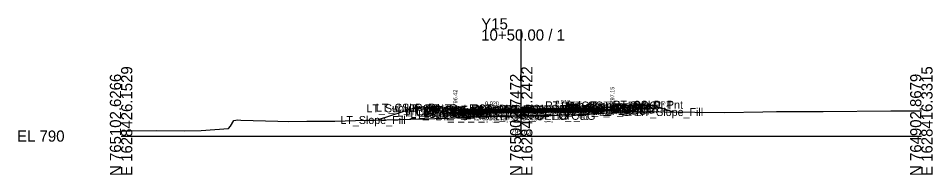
# Model space of a CAD drawing. Extents: x -26 to 203, y -10 to 2522.
# Drawn here: x -25.7 to 202.8, y 990.3 to 1029.5 of the extents above; entities that cross this region are included whole.
import ezdxf

# ---------------------------------------------------------------- set-up
doc = ezdxf.new("R2010")
doc.units = 0
for name, color, linetype in [('Default', 7, 'Continuous'), ('Exist CMT Pavement', 7, 'Continuous'), ('Exist Cross Section Cell', 7, 'Continuous'), ('Exist XS Center Line Elevation Label', 7, 'Continuous'), ('Exist XS Ground Line', 7, 'Continuous'), ('Prop CMT Conc Surface', 7, 'Continuous'), ('Prop CMT Concrete Structures', 7, 'Continuous'), ('Prop CMT Pvmt Course 1', 7, 'Continuous'), ('Prop CMT Pvmt Course 1 CG', 7, 'Continuous'), ('Prop CMT Pvmt Course 1 Wedge', 7, 'Continuous'), ('Prop CMT Pvmt Course 2', 7, 'Continuous'), ('Prop CMT Pvmt Course 2 Wedge', 7, 'Continuous'), ('Prop CMT Pvmt Course 3', 7, 'Continuous'), ('Prop CMT Pvmt Course 3 Wedge', 7, 'Continuous'), ('Prop CMT Pvmt Surface', 7, 'Continuous'), ('Prop CMT Pvmt Wedge Surface 1', 7, 'Continuous'), ('Prop CMT Pvmt Wedge Surface 2', 7, 'Continuous'), ('Prop CMT Pvmt Wedge Surface 3', 7, 'Continuous'), ('Prop CMT Slope Grass', 7, 'Continuous'), ('Prop CMT Subgrade Earthwork', 7, 'Continuous'), ('Prop XS Hydro Elevations', 7, 'Continuous'), ('Prop XS SE Text', 7, 'Continuous'), ('Prop XS Side Slope Text', 7, 'Continuous'), ('Scratch_Level_0', 7, 'Continuous')]:
    doc.layers.add(name, color=color, linetype=linetype)

msp = doc.modelspace()

# ---------------------------------------------------------------- linework, layer by layer
at = {"layer": 'Exist CMT Pavement'}
for points in [[(100, 1005.03), (97.47, 1005.02), (93.61, 1004.96)], [(100, 1005.03), (106.07, 1005.07)]]:
    msp.add_lwpolyline(points, dxfattribs=at)
at = {"layer": 'Exist Cross Section Cell'}
for p, q in [((100, 1000), (100, 1026.72)), ((0, 1000), (100, 1000)), ((100, 1000), (200, 1000))]:
    msp.add_line(p, q, dxfattribs=at)
at = {"layer": 'Exist XS Ground Line'}
msp.add_lwpolyline([(0, 1001.31), (2.3, 1001.35), (8.93, 1001.42), (15.94, 1001.31), (20.04, 1001.43), (26.82, 1001.87), (27.31, 1002.52), (28.21, 1003.89), (29.2, 1004.06), (29.91, 1003.96), (39.18, 1003.76), (41.81, 1003.68), (46.46, 1003.71), (53.42, 1003.77), (61.16, 1003.96), (63.29, 1004.01), (75.46, 1004.3), (78.43, 1004.39), (81.9, 1004.51), (89.39, 1004.87), (91.26, 1004.91), (93.18, 1005.01), (93.61, 1004.96), (97.47, 1005.02), (100, 1005.03), (106.07, 1005.07), (110.25, 1005.34), (111.48, 1005.34), (114.03, 1005.39), (115.06, 1005.39), (119.22, 1005.62), (125.22, 1006.04), (127.02, 1006.11), (128.5, 1006.12), (150.81, 1005.9), (160.35, 1006.1), (163.8, 1006.17), (175.48, 1006.17), (192.39, 1006.31), (199.37, 1006.34), (200, 1006.34)], dxfattribs=at)
at = {"layer": 'Prop CMT Conc Surface'}
for points in [[(83.51, 1006.42), (83.51, 1006.92), (83.01, 1006.92)], [(85.51, 1006.54), (83.51, 1006.42)], [(120.76, 1007.19), (122.76, 1007.15)], [(122.76, 1007.15), (122.76, 1007.65), (123.26, 1007.65)]]:
    msp.add_lwpolyline(points, dxfattribs=at)
at = {"layer": 'Prop CMT Concrete Structures'}
for points in [[(85.51, 1006.54), (83.51, 1006.42), (83.51, 1006.92), (83.01, 1006.92)], [(83.01, 1006.92), (83.01, 1005.91), (85.51, 1005.96)], [(85.51, 1005.96), (85.51, 1006.54)], [(120.76, 1007.19), (122.76, 1007.15), (122.76, 1007.65), (123.26, 1007.65)], [(123.26, 1007.65), (123.26, 1006.65), (120.76, 1006.61)], [(120.76, 1006.61), (120.76, 1007.19)]]:
    msp.add_lwpolyline(points, dxfattribs=at)
at = {"layer": 'Prop CMT Pvmt Course 1'}
for points in [[(100, 1006.83), (85.51, 1006.54)], [(85.51, 1006.29), (100, 1006.58)], [(85.51, 1006.54), (85.51, 1006.29)], [(100, 1006.83), (120.76, 1007.19)], [(120.76, 1006.94), (100, 1006.58)], [(100, 1006.58), (100, 1006.83)], [(100, 1006.58), (100, 1006.83)], [(100, 1006.7), (100, 1006.58), (100, 1006.58)], [(100, 1006.7), (100, 1006.58), (100, 1006.58)], [(120.76, 1007.19), (120.76, 1006.94)]]:
    msp.add_lwpolyline(points, dxfattribs=at)
at = {"layer": 'Prop CMT Pvmt Course 1 CG'}
for points in [[(85.51, 1005.96), (82.51, 1005.9), (82.17, 1005.56)], [(82.17, 1005.56), (85.51, 1005.62)], [(85.51, 1005.62), (85.51, 1005.96)], [(120.76, 1006.61), (123.76, 1006.66), (124.09, 1006.33)], [(120.76, 1006.28), (120.76, 1006.61)], [(124.09, 1006.33), (120.76, 1006.28)]]:
    msp.add_lwpolyline(points, dxfattribs=at)
at = {"layer": 'Prop CMT Pvmt Course 1 Wedge'}
for points in [[(100, 1006.7), (100, 1006.58)], [(100, 1006.58), (100, 1006.7)]]:
    msp.add_lwpolyline(points, dxfattribs=at)
at = {"layer": 'Prop CMT Pvmt Course 2'}
for points in [[(100, 1006.58), (85.51, 1006.29)], [(85.51, 1006.29), (85.51, 1005.96)], [(85.51, 1005.96), (100, 1006.25)], [(100, 1006.58), (120.76, 1006.94)], [(120.76, 1006.61), (100, 1006.25)], [(120.76, 1006.94), (120.76, 1006.61)]]:
    msp.add_lwpolyline(points, dxfattribs=at)
at = {"layer": 'Prop CMT Pvmt Course 2 Wedge'}
for points in [[(100, 1006.58), (100, 1006.25)], [(100, 1006.25), (100, 1006.58)]]:
    msp.add_lwpolyline(points, dxfattribs=at)
at = {"layer": 'Prop CMT Pvmt Course 3'}
for points in [[(100, 1006.25), (85.51, 1005.96)], [(85.51, 1005.96), (85.51, 1005.62)], [(85.51, 1005.62), (100, 1005.91)], [(100, 1006.25), (120.76, 1006.61)], [(120.76, 1006.28), (100, 1005.91)], [(120.76, 1006.61), (120.76, 1006.28)]]:
    msp.add_lwpolyline(points, dxfattribs=at)
at = {"layer": 'Prop CMT Pvmt Course 3 Wedge'}
for points in [[(100, 1006.25), (100, 1005.03)], [(100, 1005.03), (100, 1006.25)], [(100, 1005.03), (97.47, 1005.02), (93.61, 1004.96)], [(106.07, 1005.07), (100, 1005.03)]]:
    msp.add_lwpolyline(points, dxfattribs=at)
at = {"layer": 'Prop CMT Pvmt Surface'}
for points in [[(100, 1006.83), (85.51, 1006.54)], [(100, 1006.83), (120.76, 1007.19)]]:
    msp.add_lwpolyline(points, dxfattribs=at)
at = {"layer": 'Prop CMT Pvmt Wedge Surface 1'}
for points in [[(100, 1006.58), (85.51, 1006.29)], [(85.51, 1006.29), (85.51, 1006.54)], [(100, 1006.58), (120.76, 1006.94)], [(120.76, 1006.94), (120.76, 1007.19)]]:
    msp.add_lwpolyline(points, dxfattribs=at)
at = {"layer": 'Prop CMT Pvmt Wedge Surface 2'}
for points in [[(85.51, 1006.29), (85.51, 1006.54)], [(120.76, 1006.94), (120.76, 1007.19)]]:
    msp.add_lwpolyline(points, dxfattribs=at)
at = {"layer": 'Prop CMT Pvmt Wedge Surface 3'}
for points in [[(85.51, 1005.96), (85.51, 1006.54)], [(120.76, 1006.61), (120.76, 1007.19)]]:
    msp.add_lwpolyline(points, dxfattribs=at)
at = {"layer": 'Prop CMT Slope Grass'}
for points in [[(123.26, 1007.65), (132.76, 1007.84), (138.21, 1006.02)], [(83.01, 1006.92), (73.51, 1007.11), (64.28, 1004.03)]]:
    msp.add_lwpolyline(points, dxfattribs=at)
at = {"layer": 'Prop CMT Subgrade Earthwork'}
for points in [[(85.51, 1005.62), (82.17, 1005.56), (80.77, 1006.96)], [(100, 1005.91), (85.51, 1005.62)], [(100, 1005.91), (120.76, 1006.28)], [(120.76, 1006.28), (124.09, 1006.33), (125.44, 1007.69)]]:
    msp.add_lwpolyline(points, dxfattribs=at)

# ---------------------------------------------------------------- texts
at = {"layer": 'Default'}
msp.add_text('-', height=0.0001, dxfattribs=at).set_placement((0, 1000))
at = {"layer": 'Exist Cross Section Cell'}
for s, p in [('Y15', (90, 1026.72)), ('10+50.00 / 1', (90, 1023.92)), ('EL 790', (-26, 998.6))]:
    msp.add_text(s, height=2.8, dxfattribs=at).set_placement(p)
for s, p in [('E 1628426.1529', (2.8, 990)), ('E 1628421.2422', (102.8, 990)), ('E 1628416.3315', (202.8, 990)), ('N 765102.6266', (0, 990)), ('N 765002.7472', (100, 990)), ('N 764902.8679', (200, 990))]:
    msp.add_text(s, height=2.8, rotation=90, dxfattribs=at).set_placement(p)
at = {"layer": 'Exist XS Center Line Elevation Label'}
msp.add_text('795.03', height=1.2, dxfattribs=at).set_placement((97.42, 1000.43))
at = {"layer": 'Prop XS Hydro Elevations'}
for s, p in [('796.42', (84.01, 1007.42)), ('797.15', (123.26, 1008.15))]:
    msp.add_text(s, height=1, rotation=90, dxfattribs=at).set_placement(p)
at = {"layer": 'Prop XS SE Text'}
for s, rotation, p in [('0.020', 1.1458, (90.99, 1007.65)), ('0.017', 1.0026, (108.73, 1007.98))]:
    msp.add_text(s, height=1, rotation=rotation, dxfattribs=at).set_placement(p)
at = {"layer": 'Prop XS Side Slope Text'}
for rotation, p in [(341.5668, (134.97, 1007.89)), (18.4332, (67.91, 1006.03))]:
    msp.add_text('3:1', height=1, rotation=rotation, dxfattribs=at).set_placement(p)
at = {"layer": 'Scratch_Level_0'}
for s, p in [('LT_Sub_Trench_Out_DLT', (61.33, 1005.96)), ('LT_CSLP_Pnt', (63.69, 1006.11)), ('LT_CG_Top_Face', (70.77, 1005.92)), ('LT_CG_Top_BOC', (71.3, 1005.92)), ('PV1_PGL', (94.47, 1005.83)), ('RT_PV1_OEEOP', (95.89, 1005.81)), ('RT_Sub_Trench_Out_DLT', (105.96, 1006.69)), ('RT_CG_Top_Face', (109.97, 1006.65)), ('RT_PV2_OEOT', (110.88, 1005.94)), ('RT_CG_Top_Gut', (110.95, 1006.15)), ('RT_PV1_OEOT', (111.45, 1006.19)), ('RT_CG_Top_BOC', (111.5, 1006.65)), ('RT_CSLP_Pnt', (122.89, 1006.84)), ('LT_CG1_Shelf_Out', (69.06, 1004.9)), ('LT_CG_Bot_BOC', (71.33, 1004.91)), ('LT_CG_Top_Gut', (71.75, 1005.42)), ('LT_Sub_OEOP', (72.28, 1004.56)), ('LT_CG_Bot_IE', (75.43, 1004.96)), ('LT_Sub_OEOT', (75.59, 1004.62)), ('LT_PV2_OEOT', (75.69, 1005.29)), ('LT_PV3_OEOT', (75.69, 1004.96)), ('LT_PV1_OEOT', (76.25, 1005.54)), ('LT_PV_Sub_Tie_Out', (78.57, 1003.96)), ('LT_PV_OEEOP_EG', (81.15, 1003.96)), ('LT_Sub_OEEOP', (82.82, 1004.78)), ('LT_PV2_OEEOP', (82.91, 1005.45)), ('LT_PV3_OEEOP', (82.91, 1005.12)), ('LT_PV1_OEEOP', (83.48, 1005.58)), ('RT_PV_IEEOP_EG', (88.14, 1004.03)), ('LT_PV_IEEOP_EG', (88.19, 1004.03)), ('RT_PV2_IEEOP', (89.91, 1005.58)), ('RT_PV3_IEEOP', (89.91, 1005.25)), ('LT_PV2_IEEOP', (89.95, 1005.58)), ('LT_PV3_IEEOP', (89.95, 1005.25)), ('RT_PV1_IEEOP', (90.47, 1005.7)), ('LT_PV1_IEEOP', (90.52, 1005.7)), ('RT_PV_Sub_Tie_Out', (90.95, 1004.07)), ('RT_PV_OEEOP_EG', (93.56, 1004.07)), ('PV2_PGL', (93.91, 1005.58)), ('RT_Sub_OEEOP', (95.23, 1005.02)), ('RT_PV2_OEEOP', (95.33, 1005.69)), ('RT_PV3_OEEOP', (95.33, 1005.35)), ('RT_CG1_Shelf_Out', (110.26, 1005.66)), ('RT_CG_Bot_IE', (110.62, 1005.61)), ('RT_Sub_OEOT', (110.79, 1005.28)), ('RT_PV3_OEOT', (110.88, 1005.61)), ('RT_CG_Bot_BOC', (111.53, 1005.65)), ('RT_Sub_OEOP', (114.15, 1005.33)), ('RT_Slope_Fill', (128.68, 1005.02)), ('LT_Slope_Fill', (54.8, 1003.03))]:
    msp.add_text(s, height=2, dxfattribs=at).set_placement(p)

doc.saveas('drawing.dxf')
